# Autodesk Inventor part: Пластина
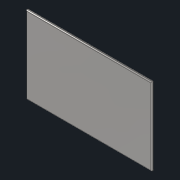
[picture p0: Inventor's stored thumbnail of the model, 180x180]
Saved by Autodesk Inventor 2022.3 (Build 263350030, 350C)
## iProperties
Created: 2022-08
Part Number: Пластина
Material: Сталь 40ХНМА
Document SubType Name: Sheet Metal
Designer: Карташов
Density: 7.85 g/cm^3
Sheet Metal Rule: По умолчанию
Appearance: С умеренной полировкой
Author: Карташов
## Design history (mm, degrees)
node "Грань1"
  sketch "Эскиз1"
    geometry: L1 (-73, -45)-(73, -45); L2 (73, -45)-(73, 45); L3 (73, 45)-(-73, 45); L4 (-73, 45)-(-73, -45); L5 (-73, -45)-(73, 45); L6 (73, -45)-(-73, 45); 1 further point
    constraints: 12 end point, 2 midpoint, 2 parallel, 1 horizontal, 1 perpendicular
    dimensions: "d0" = 146 distance of L3.end L2.end; "d1" = 90 distance of L2.end L1.end
fillet "Сопряжение1" dims "d3" = 1
node "Твердое тело1"
feature "Пластина1" dims "d2" = 3 (= Толщина)
other parameters: "Толщина" = 3 (derived), "Поправка" = 4.4, "Радиус_гибки" = 3 (= Толщина), "Ширина_просечки" = 3 (= Толщина), "Глубина_просечки" = 1.5 (= 0.5 x Толщина), "Размер_просечки" = 12 (= 4 x Толщина), "Зазор_стыка" = 0.01, "Мин_остаток" = 6 (= 2 x Толщина), "Радиус_перехода" = 3 (= Радиус_гибки), "Радиус_Якоби" = 3 (= Радиус_гибки), "Размер_зазора" = 3 (= Толщина)
